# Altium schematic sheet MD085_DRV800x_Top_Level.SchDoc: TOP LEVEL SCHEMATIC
size 431 x 279 mm; Date: Not shown in title block; ApprovedBy: Not shown in title block; CheckedBy: Not shown in title block; Author: Not shown in title block; CompanyName: Not shown in title block; DrawnBy: Keerthi Kumanan; Engineer: Not shown in title block; Organization: Not shown in title block; Address1: Not shown in title block; Address2: Not shown in title block; Address3: Not shown in title block; Address4: Not shown in title block; DocumentNumber: 2; Revision: Use project parameter SCH_Rev; SheetNumber: 1; SheetTotal: 3; PageSetup: Record=PageOptions¦CenterHorizontal=True¦CenterVertical=True¦PrintScale=1.00¦XCorrection=1.00¦YCorrection=1.00¦PrintKind=0¦BorderSize=5000000¦LeftOffset=0¦BottomOffset=0¦Orientation=2¦PaperLength=1000¦PaperWidth=1000¦Scale=100¦PaperSource=15¦PrintQuality=600¦MediaType=1¦DitherType=10¦PaperKind=Letter¦PrintScaleMode=1
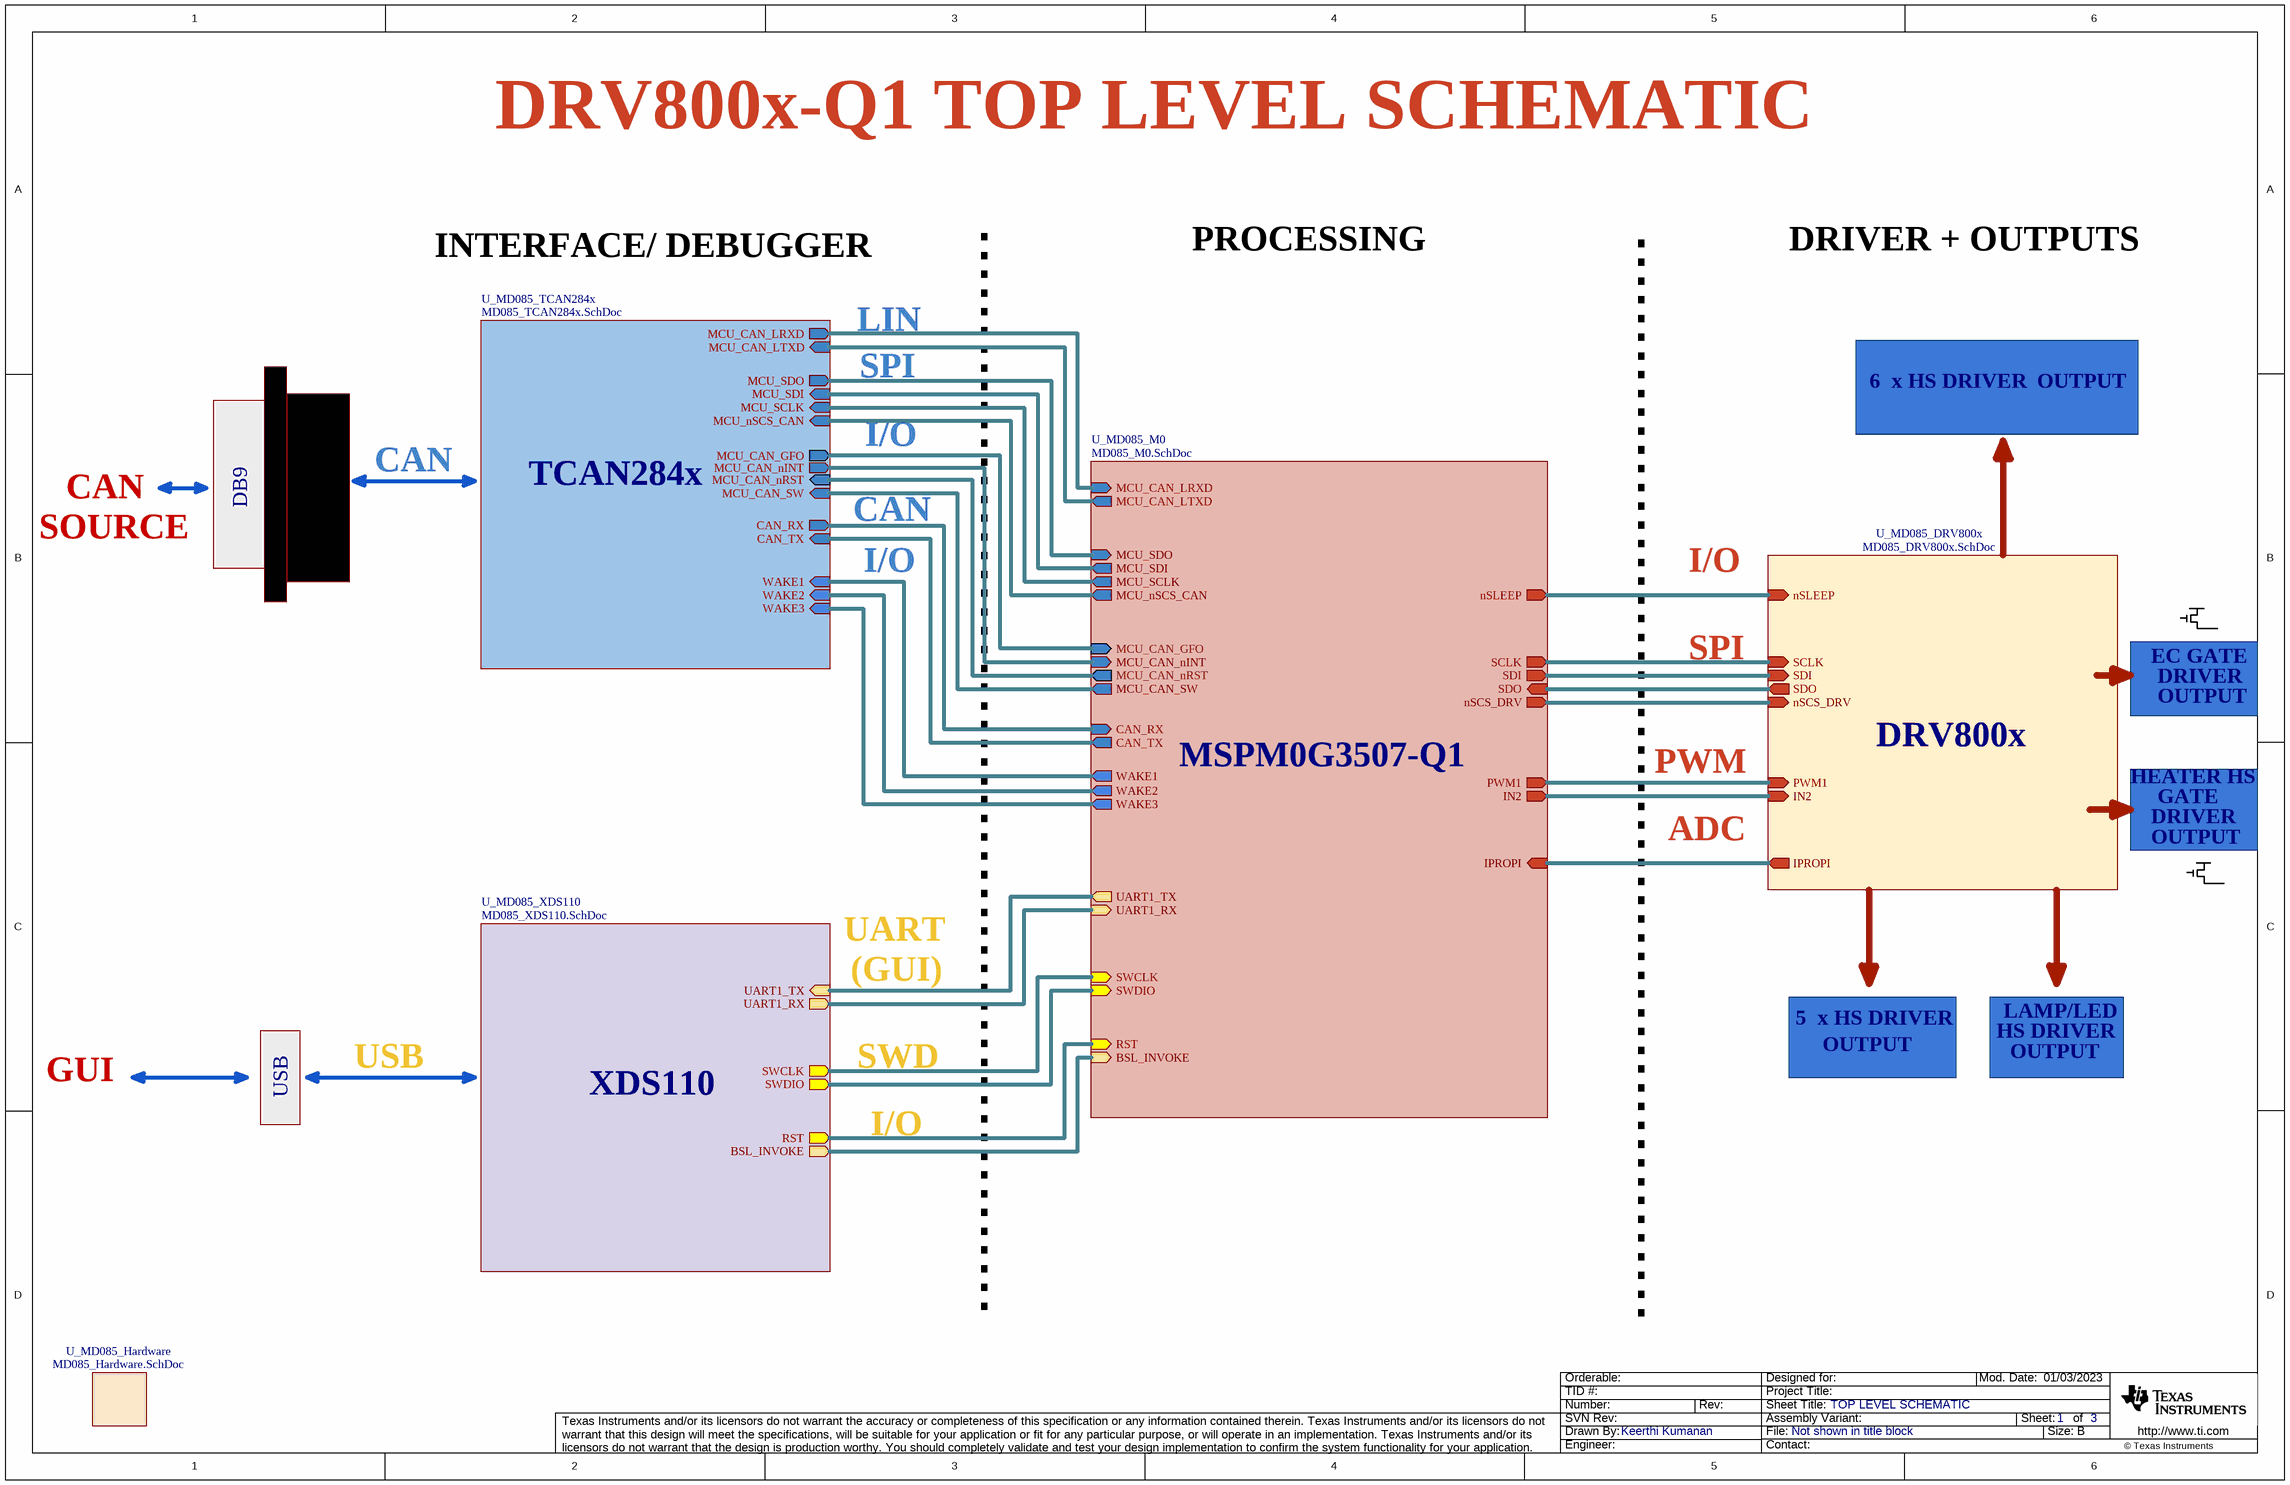
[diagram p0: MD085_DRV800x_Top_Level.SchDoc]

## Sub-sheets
U_MD085_DRV800x = MD085_DRV800x.SchDoc: PWM1 (in), SDI (in), SDO (out), SCLK (in), nSLEEP (in), nSCS_DRV (in), IN2 (in), IPROPI (out)
U_MD085_Hardware = MD085_Hardware.SchDoc: no entries
U_MD085_M0 = MD085_M0.SchDoc: SWDIO (in), SWCLK (in), PWM1 (out), SDI (out), SDO (in), SCLK (out), nSLEEP (out), CAN_TX (out), CAN_RX (in), RST (in), MCU_CAN_GFO (in), MCU_CAN_nRST (out), MCU_CAN_LTXD (out), MCU_CAN_LRXD (in), MCU_nSCS_CAN (out), MCU_SDO (in), MCU_SDI (out), MCU_SCLK (out), nSCS_DRV (out), MCU_CAN_SW (out), MCU_CAN_nINT (in), UART1_TX (out), UART1_RX (in), BSL_INVOKE (in), WAKE1 (out), WAKE2 (out), WAKE3 (out), IN2 (out), IPROPI (in)
U_MD085_TCAN284x = MD085_TCAN284x.SchDoc: CAN_TX (in), CAN_RX (out), MCU_CAN_GFO (out), MCU_CAN_nRST (in), MCU_CAN_LTXD (in), MCU_CAN_LRXD (out), MCU_nSCS_CAN (in), MCU_SDO (out), MCU_SDI (in), MCU_SCLK (in), MCU_CAN_SW (in), MCU_CAN_nINT (out), WAKE1 (in), WAKE2 (in), WAKE3 (in)
U_MD085_XDS110 = MD085_XDS110.SchDoc: SWDIO (out), SWCLK (out), RST (out), UART1_RX (out), UART1_TX (in), BSL_INVOKE (out)

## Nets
(unnamed): sheet U_MD085_XDS110/SWDIO, sheet U_MD085_M0/SWDIO
(unnamed): sheet U_MD085_XDS110/SWCLK, sheet U_MD085_M0/SWCLK  [a separate net that carries the same name]
(unnamed): sheet U_MD085_XDS110/RST, sheet U_MD085_M0/RST  [a separate net that carries the same name]
(unnamed): sheet U_MD085_XDS110/UART1_RX, sheet U_MD085_M0/UART1_RX  [a separate net that carries the same name]
(unnamed): sheet U_MD085_XDS110/UART1_TX, sheet U_MD085_M0/UART1_TX  [a separate net that carries the same name]
(unnamed): sheet U_MD085_XDS110/BSL_INVOKE, sheet U_MD085_M0/BSL_INVOKE  [a separate net that carries the same name]
(unnamed): sheet U_MD085_M0/PWM1, sheet U_MD085_DRV800x/PWM1  [a separate net that carries the same name]
(unnamed): sheet U_MD085_M0/SDI, sheet U_MD085_DRV800x/SDI  [a separate net that carries the same name]
(unnamed): sheet U_MD085_M0/SDO, sheet U_MD085_DRV800x/SDO  [a separate net that carries the same name]
(unnamed): sheet U_MD085_M0/SCLK, sheet U_MD085_DRV800x/SCLK  [a separate net that carries the same name]
(unnamed): sheet U_MD085_M0/nSLEEP, sheet U_MD085_DRV800x/nSLEEP  [a separate net that carries the same name]
(unnamed): sheet U_MD085_M0/CAN_TX, sheet U_MD085_TCAN284x/CAN_TX  [a separate net that carries the same name]
(unnamed): sheet U_MD085_M0/CAN_RX, sheet U_MD085_TCAN284x/CAN_RX  [a separate net that carries the same name]
(unnamed): sheet U_MD085_M0/MCU_CAN_GFO, sheet U_MD085_TCAN284x/MCU_CAN_GFO  [a separate net that carries the same name]
(unnamed): sheet U_MD085_M0/MCU_CAN_nRST, sheet U_MD085_TCAN284x/MCU_CAN_nRST  [a separate net that carries the same name]
(unnamed): sheet U_MD085_M0/MCU_CAN_LTXD, sheet U_MD085_TCAN284x/MCU_CAN_LTXD  [a separate net that carries the same name]
(unnamed): sheet U_MD085_M0/MCU_CAN_LRXD, sheet U_MD085_TCAN284x/MCU_CAN_LRXD  [a separate net that carries the same name]
(unnamed): sheet U_MD085_M0/MCU_nSCS_CAN, sheet U_MD085_TCAN284x/MCU_nSCS_CAN  [a separate net that carries the same name]
(unnamed): sheet U_MD085_M0/MCU_SDO, sheet U_MD085_TCAN284x/MCU_SDO  [a separate net that carries the same name]
(unnamed): sheet U_MD085_M0/MCU_SDI, sheet U_MD085_TCAN284x/MCU_SDI  [a separate net that carries the same name]
(unnamed): sheet U_MD085_M0/MCU_SCLK, sheet U_MD085_TCAN284x/MCU_SCLK  [a separate net that carries the same name]
(unnamed): sheet U_MD085_M0/nSCS_DRV, sheet U_MD085_DRV800x/nSCS_DRV  [a separate net that carries the same name]
(unnamed): sheet U_MD085_M0/MCU_CAN_SW, sheet U_MD085_TCAN284x/MCU_CAN_SW  [a separate net that carries the same name]
(unnamed): sheet U_MD085_M0/MCU_CAN_nINT, sheet U_MD085_TCAN284x/MCU_CAN_nINT  [a separate net that carries the same name]
(unnamed): sheet U_MD085_M0/WAKE1, sheet U_MD085_TCAN284x/WAKE1  [a separate net that carries the same name]
(unnamed): sheet U_MD085_M0/WAKE2, sheet U_MD085_TCAN284x/WAKE2  [a separate net that carries the same name]
(unnamed): sheet U_MD085_M0/WAKE3, sheet U_MD085_TCAN284x/WAKE3  [a separate net that carries the same name]
(unnamed): sheet U_MD085_M0/IN2, sheet U_MD085_DRV800x/IN2  [a separate net that carries the same name]
(unnamed): sheet U_MD085_M0/IPROPI, sheet U_MD085_DRV800x/IPROPI  [a separate net that carries the same name]

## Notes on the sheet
- DRV800x-Q1 TOP LEVEL SCHEMATIC
- INTERFACE/ DEBUGGER
- PROCESSING
- DRIVER + OUTPUTS
- LIN
- SPI
- 6  x HS DRIVER
- OUTPUT
- CAN
- TCAN284x
- I/O
- SOURCE
- DB9
- EC GATE
- DRIVER
- DRV800x
- MSPM0G3507-Q1
- PWM
- HEATER HS
- GATE
- ADC
- UART
- (GUI)
- 5  x HS DRIVER
- LAMP/LED
- GUI
- USB
- XDS110
- SWD
- HS DRIVER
